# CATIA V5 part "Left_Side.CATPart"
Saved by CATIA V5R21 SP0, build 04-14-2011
Part number: Left_Side
Bounding box of the stored display mesh (mm): x -172.8 to 2.8, y 0 to 2.8, z -5 to 133.511
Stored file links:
  C:\Users\Pouria\Desktop\Box\Assembled\Left_Side.CATPart
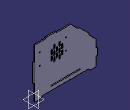
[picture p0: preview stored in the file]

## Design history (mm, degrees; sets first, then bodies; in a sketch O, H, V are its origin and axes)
Body1 (main body)
  Sketch1 on zx-plane, origin (0, 0, 0), H (-1, 0, 0), V (0, 0, 1)
    line L1 (0, 0) -> (0, 40)
    line L2 (0, 130.7107) -> (30, 130.7107)
    point P2 (99.2893, 130.7107)
    line L3 (99.2893, 130.7107) -> (120.5025, 109.4975)
    point P3 (170, 60)
    line L4 (170, 60) -> (170, 40)
    point P4 (170, 0)
    line L5 (147.8, 0) -> (22.2, 0)
    line L6 (45, 12.8) -> (125, 12.8)
    line L7 (125, 12.8) -> (125, 10)
    line L8 (125, 10) -> (45, 10)
    line L9 (45, 10) -> (45, 12.8)
    line L10 (147.8, 0) -> (152.8, -5)
    line L11 (152.8, -5) -> (170, -5)
    point P11 (170, -5)
    line L12 (170, -5) -> (170, 0)
    line L13 (0, 0) -> (0, -5)
    line L14 (0, -5) -> (17.2, -5)
    line L15 (17.2, -5) -> (22.2, 0)
    circle A1 centre (14, 106.7107) radius 1.5
    point P15 (14, 106.7107)
    circle A2 centre (14, 74.7107) radius 1.5
    point P16 (14, 74.7107)
    circle A3 centre (86, 106.7107) radius 1.5
    point P17 (86, 106.7107)
    circle A4 centre (86, 74.7107) radius 1.5
    point P18 (86, 74.7107)
    line L16 (120.5025, 109.4975) -> (122.4824, 111.4774)
    line L17 (122.4824, 111.4774) -> (150.7667, 83.1931)
    line L18 (150.7667, 83.1931) -> (148.7868, 81.2132)
    point P22 (148.7868, 81.2132)
    line L19 (148.7868, 81.2132) -> (170, 60)
    line L20 (30, 130.7107) -> (30, 133.5107)
    line L21 (30, 133.5107) -> (60, 133.5107)
    line L22 (60, 133.5107) -> (60, 130.7107)
    point P26 (60, 130.7107)
    line L23 (170, 40) -> (172.8, 40)
    line L24 (172.8, 40) -> (172.8, 20)
    line L25 (172.8, 20) -> (170, 20)
    point P30 (170, 20)
    line L26 (170, 20) -> (170, 0)
    line L27 (60, 130.7107) -> (99.2893, 130.7107)
    point P31 (0, 90)
    line L28 (0, 90) -> (-2.8, 90)
    line L29 (-2.8, 90) -> (-2.8, 40)
    line L30 (-2.8, 40) -> (0, 40)
    line L31 (0, 90) -> (0, 130.7107)
    length L6 = 80
    distance L8 L6 = 2.8
    distance L7 L4 = 45
    distance L8 L5 = 10
    angle L3 L4 = 135
    angle L10 L5 = 45
    length L12 = 5
    length L11 = 17.2
    length L14 = 17.2
    length L13 = 5
    angle L5 L15 = 45
    distance P4 O = 170
    length L5 = 125.6
    distance P18 P17 H = 0
    distance P16 P15 H = 0
    distance P17 P15 V = 0
    distance P18 P16 V = 0
    distance P18 P16 = 72
    distance P15 P16 = 32
    radius A1 = 1.5
    radius A3 = 1.5
    radius A4 = 1.5
    radius A2 = 1.5
    distance P15 L2 = 24
    distance P15 L1 = 14
    length L17 = 40
    distance L17 L3 = 2.8
    distance L18 P3 = 30
    distance P2 P3 = 100
    length L24 = 20
    length L23 = 2.8
    distance L25 L5 = 20
    distance P3 P4 = 60
    length L21 = 30
    distance L20 L1 = 30
    distance L21 L2 = 2.8
    length L29 = 50
    distance L5 L30 = 40
    distance L29 L1 = 2.8
    vertical: L1 V, L4 V, L7 V, L9 V, L12 V, L13 V, L20 V, L22 V, L24 V, L26 V, L29 V, L31 V
    horizontal: L2 H, L5 H, L6 H, L8 H, L11 H, L14 H, L21 H, L23 H, L25 H, L27 H, L28 H, L30 H
    coincidence: P4 H, P11 L4, L12 L4, L13 L1, P22 L3, L3 L19, P26 L2, P30 L4, L4 L26, L2 L27, P31 L1, L1 L31
    perpendicularity: L18 L3, L16 L3
  Pad1: profile Sketch1, direction (0, 1, 0), length 2.8
  Sketch2 on end face of Pad1, origin (0, 2.8, 0), H (-1, 0, 0), V (0, 0, 1)
    line L1 (77.5, 81.7107) -> (73.5, 81.7107)
    line L2 (73.5, 81.7107) -> (73.5, 69.7107)
    line L3 (73.5, 69.7107) -> (77.5, 69.7107)
    line L4 (77.5, 69.7107) -> (77.5, 81.7107)
    reference projected circle E1 centre (86, 74.7107) radius 1.5 from edge [end face of Pad1 | face of Pad1 from Sketch1.A4]
    reference projected circle E2 centre (86, 74.7107) radius 1.5 from edge [end face of Pad1 | face of Pad1 from Sketch1.A4]
    distance L3 E1 = 3.5
    distance L4 E2 = 10
    length L3 = 4
    length L2 = 12
    horizontal: L1 H, L3 H
    vertical: L2 V, L4 V
  Pocket1: profile Sketch2, direction (0, -1, 0), through (limit type 3)
  RectPattern1: of Pocket1, direction 1 instances 3, spacing 14, along edge [end face of Pad1 | face of Pad1 from Sketch1.L6], direction 2 instances 3, spacing 15, along edge [face of Pad1 from Sketch1.L29 | end face of Pad1] reversed
  Sketch3 on end face of Pad1, origin (0, 2.8, 0), H (-1, 0, 0), V (0, 0, 1)
    line L1 (66.5, 75.7107) -> (70.5, 75.7107)
    line L2 (70.5, 75.7107) -> (70.5, 63.7107)
    line L3 (70.5, 63.7107) -> (66.5, 63.7107)
    line L4 (66.5, 63.7107) -> (66.5, 75.7107)
    reference projected line E1 (73.5, 81.7107) -> (73.5, 69.7107) from edge [end face of Pad1 | face of Pocket1 from Sketch2.L2]
    reference projected line E2 (73.5, 69.7107) -> (77.5, 69.7107) from edge [end face of Pad1 | face of Pocket1 from Sketch2.L3]
    distance L2 E1 = 3
    length L2 = 12
    length L3 = 4
    distance L3 E2 = 6
    horizontal: L1 H, L3 H
    vertical: L2 V, L4 V
  Pocket2: profile Sketch3, direction (0, -1, 0), through (limit type 3)
  RectPattern2: of Pocket2, direction 1 instances 2, spacing 14, along edge [face of Pad1 from Sketch1.L27 | end face of Pad1], direction 2 instances 3, spacing 15, along edge [face of Pad1 from Sketch1.L31 | end face of Pad1] reversed
  Fillet1: radius 1, on edge [face of RectPattern1 | face of RectPattern1] (x32); edge [face of RectPattern2 | face of RectPattern2] (x20); edge [face of Pocket1 from Sketch2.L2 | face of Pocket1 from Sketch2.L1]; edge [face of Pocket2 from Sketch3.L4 | face of Pocket2 from Sketch3.L1]; edge [face of Pocket2 from Sketch3.L3 | face of Pocket2 from Sketch3.L4]; edge [face of Pocket1 from Sketch2.L3 | face of Pocket1 from Sketch2.L2]; edge [face of Pocket1 from Sketch2.L1 | face of Pocket1 from Sketch2.L4]; edge [face of Pocket2 from Sketch3.L1 | face of Pocket2 from Sketch3.L2]; edge [face of Pocket2 from Sketch3.L2 | face of Pocket2 from Sketch3.L3]; edge [face of Pocket1 from Sketch2.L4 | face of Pocket1 from Sketch2.L3]
  Sketch4 on end face of Pad1, origin (0, 2.8, 0), H (-1, 0, 0), V (0, 0, 1)
    line L1 (78.7193, 113.3506) -> (72.6493, 113.3506)
    line L2 (72.6493, 113.3506) -> (72.6493, 98.8904)
    line L3 (72.6493, 98.8904) -> (78.7193, 98.8904)
    line L4 (78.7193, 98.8904) -> (78.7193, 113.3506)
    point P5 (64.9239, 113.3506)
    line L5 (64.9239, 113.3506) -> (58.0813, 113.3506)
    line L6 (58.0813, 113.3506) -> (58.0813, 98.8904)
    line L7 (58.0813, 98.8904) -> (64.9239, 98.8904)
    line L8 (64.9239, 98.8904) -> (64.9239, 113.3506)
    point P7 (58.0813, 98.8904)
    line L9 (50.4662, 112.7031) -> (43.8443, 112.7031)
    line L10 (43.8443, 112.7031) -> (43.8443, 98.8904)
    line L11 (43.8443, 98.8904) -> (50.4662, 98.8904)
    line L12 (50.4662, 98.8904) -> (50.4662, 112.7031)
    point P11 (43.8443, 98.8904)
    horizontal: L1 H, L3 H, L5 H, L7 H, L9 H, L11 H
    vertical: L2 V, L4 V, L6 V, L8 V, L10 V, L12 V
    coincidence: P5 L1, P7 L3, P11 L3
  Pad2: profile Sketch4, direction (0, 1, 0), up to start face of Pad1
